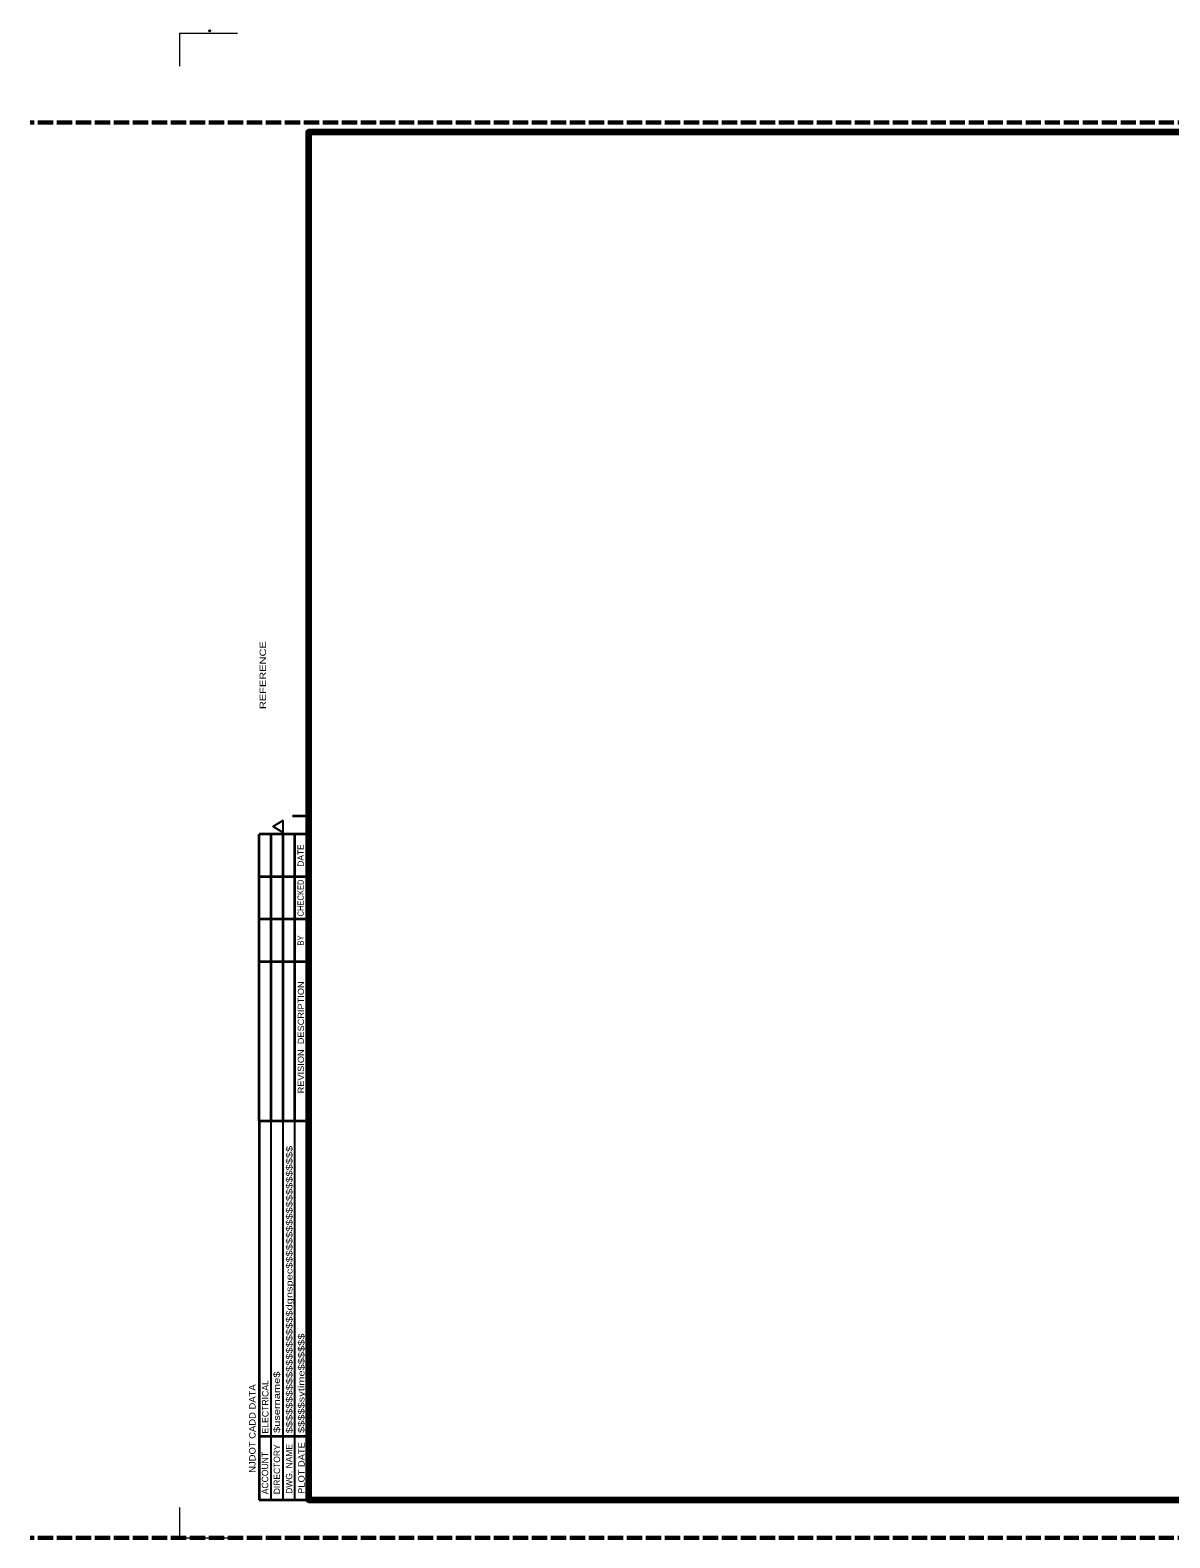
# Model space of a CAD drawing. Extents: x 214293 to 215244, y 214345 to 214808.
# Drawn here: x 214973.8 to 215108.8, y 214618.2 to 214796.7 of the extents above; entities that cross this region are included whole.
import ezdxf
from ezdxf.enums import TextEntityAlignment as Align

# ---------------------------------------------------------------- set-up
doc = ezdxf.new("R2010")
doc.units = 0
doc.header["$LTSCALE"] = 0.3
doc.header["$PDMODE"] = 32
doc.header["$PDSIZE"] = 0.15
doc.linetypes.add('LONG_DASHED', pattern=[7.5, 6, -1.5])
doc.layers.add('1', color=7, linetype='Continuous', lineweight=25)
doc.layers.add('25', color=7, linetype='Continuous', lineweight=35)

msp = doc.modelspace()

# ---------------------------------------------------------------- linework, layer by layer
at = {"layer": '1', "lineweight": 13}
for p, q in [((214991.4844, 214796.3568), (214991.4844, 214792.4568)), ((214991.4844, 214796.3568), (214998.3844, 214796.3568)), ((214991.4844, 214621.7568), (214991.4844, 214618.1568)), ((214991.4844, 214618.1568), (214998.3844, 214618.1568))]:
    msp.add_line(p, q, dxfattribs=at)
at = {"layer": '1', "linetype": 'LONG_DASHED', "lineweight": 60}
for p, q in [((215242.0344, 214785.7968), (214973.8104, 214785.7968)), ((215242.0344, 214618.1568), (214973.8104, 214618.1568))]:
    msp.add_line(p, q, dxfattribs=at)
at = {"layer": '1', "lineweight": 35}
for p, q in [((215004.8644, 214703.6568), (215006.7844, 214703.6568)), ((215000.9471, 214667.5483), (215006.7844, 214667.5483)), ((215000.9471, 214667.5483), (215000.9471, 214622.6568)), ((215000.9471, 214630.1929), (215006.7844, 214630.1929)), ((215000.9471, 214622.6568), (215006.7844, 214622.6568))]:
    msp.add_line(p, q, dxfattribs=at)
at = {"layer": '1'}
for p, q in [((215002.3657, 214622.6568), (215002.3657, 214667.5483)), ((215003.7844, 214622.6568), (215003.7844, 214667.5483)), ((215005.1669, 214622.6568), (215005.1669, 214667.5483))]:
    msp.add_line(p, q, dxfattribs=at)
at = {"layer": '1', "lineweight": 158}
msp.add_lwpolyline([(215239.2844, 214622.6568), (215239.2844, 214784.6568), (215006.7844, 214784.6568), (215006.7844, 214622.6568)], close=True, dxfattribs=at)
at = {"layer": '1'}
msp.add_point((214995.0844, 214796.6568), dxfattribs=at)
at = {"layer": '25'}
for p, q in [((215006.7844, 214701.4881), (215000.9471, 214701.4881)), ((215000.9471, 214667.5483), (215000.9471, 214701.4881)), ((215002.3657, 214667.5483), (215002.3657, 214701.4881)), ((215003.7844, 214667.5483), (215003.7844, 214701.4881)), ((215005.1669, 214667.5483), (215005.1669, 214701.4881)), ((215006.7844, 214696.455), (215000.9471, 214696.455)), ((215006.7844, 214691.4218), (215000.9471, 214691.4218)), ((215006.7844, 214686.3887), (215000.9471, 214686.3887)), ((215006.5856, 214686.3887), (215005.1669, 214686.3887))]:
    msp.add_line(p, q, dxfattribs=at)
at = {"layer": '25', "lineweight": 25}
msp.add_lwpolyline([(215003.7934, 214703.1146), (215002.5736, 214702.4098), (215003.7934, 214701.705)], close=True, dxfattribs=at)

# ---------------------------------------------------------------- texts
at = {"layer": '1'}
for s, height, width, p in [('REFERENCE                                                              ', 0.75, 1.3, (215001.7444, 214716.3168)), ('$$$$$$$$$$$$$$$$$$$$dgnspec$$$$$$$$$$$$$$$$$$$$', 0.7526, 1.3, (215004.8778, 214630.5363)), ('$$$$$sytime$$$$$$', 0.7526, 1.3, (215006.2964, 214630.5725)), ('$username$', 0.7526, 1.3, (215003.3958, 214630.5815)), ('NJDOT CADD DATA', 0.759, 1.1, (215000.5043, 214625.8556)), ('PLOT DATE', 0.7499, 1.1, (215006.3145, 214623.3616))]:
    msp.add_text(s, height=height, rotation=90, dxfattribs=dict(at, width=width)).set_placement(p)
for s, height, p in [('ELECTRICAL', 0.768, (215002.0404, 214630.5092)), ('ACCOUNT', 0.7589, (215002.0043, 214623.3164)), ('DIRECTORY', 0.75, (215003.4139, 214623.3255)), ('DWG. NAME', 0.75, (215004.8507, 214623.3707))]:
    msp.add_text(s, height=height, rotation=90, dxfattribs=at).set_placement(p)
at = {"layer": '25'}
msp.add_text('DATE', height=0.741, rotation=90, dxfattribs=at).set_placement((215006.2151, 214698.9781), align=Align.CENTER)
for s, width, p in [('CHECKED', 0.9, (215006.2151, 214693.9443)), ('BY', 0.9, (215006.2151, 214688.9078)), ('REVISION  DESCRIPTION', 1.1, (215006.2513, 214677.437))]:
    msp.add_text(s, height=0.741, rotation=90, dxfattribs=dict(at, width=width)).set_placement(p, align=Align.CENTER)

doc.saveas('drawing.dxf')
